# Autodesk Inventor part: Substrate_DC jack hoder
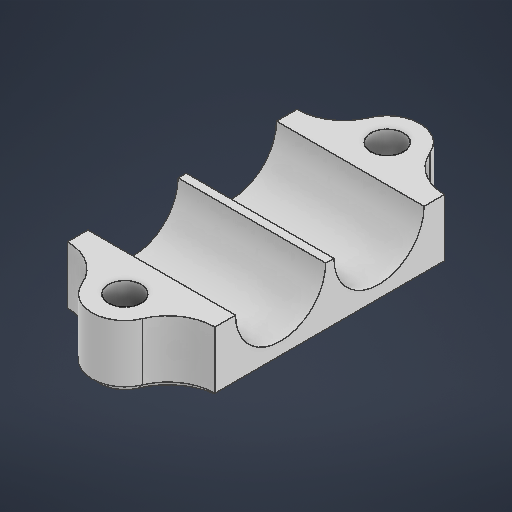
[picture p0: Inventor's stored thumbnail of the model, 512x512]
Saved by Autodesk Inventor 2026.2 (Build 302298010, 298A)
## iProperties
Created: 2026-04
Part Number: Substrate_DC jack hoder
Material: 일반
Document SubType Name: Modeling
Designer: work
Density: 1 g/cm^3
Appearance: 기본값
Author: work
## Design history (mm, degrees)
sketch "스케치1"
  geometry: L1 (0, 0)-(0, -12); L2 (0, -12)-(0, -20); L3 (0, -20)-(-8, -20); L4 (-8, -20)-(-8, 8); L5 (-8, 8)-(0, 8); L6 (0, 8)-(0, 0); C1 r 5.5 at (0, 0); C2 r 5.5 at (0, -12); 5 further points
  constraints: 12 end point, 3 perpendicular, 2 centre point, 2 coincident, 2 vertical, 1 horizontal
  dimensions: "d0" = 11 diameter of C1; "d1" = 12 distance of L1.start L1.end; "d2" = 11 diameter of C2; "d3" = 8 distance of L2.start L2.end; "d4" = 8 distance of L5.end L1.start; "d5" = 8 distance between parallel lines of L4 L6
extrude "돌출1" new body sketch "스케치1" distance "d6" = 18; taper "d7" = 0 deg
sketch "스케치2" dims "d9" = 8
  geometry: L1 (0, 2.5)-(0, 0) reference; L2 (0, 0)-(18, 0) reference; L3 (18, 2.5)-(18, 0) reference; L4 (0, 2.5)-(18, 2.5) reference; L5 (0, -23)-(18, -23) reference; L6 (0, -25.5)-(18, -25.5) reference; L7 (0, -11)-(0, -12) reference; L8 (0, -12)-(18, -12) reference; L9 (18, -11)-(18, -12) reference; L10 (0, -11)-(18, -11) reference; L11 (9, 2.5)-(9, -25.5); L12 (0, 2.5)-(18, 2.5) reference; L13 (18, -11.5)-(0, -11.5); L14 (9, -27.5)-(9, 4.5); C1 r 2 at (9, 4.5); C2 r 2 at (9, -27.5); A1 r 5.75 centre (0, 8.25) between (0, 2.5) and (5.308, 6.038); A2 r 5.75 centre (18, 8.25) between (12.692, 6.038) and (18, 2.5); A3 r 5.75 centre (18, -31.25) between (18, -25.5) and (12.692, -29.038); A4 r 5.75 centre (0, -31.25) between (5.308, -29.038) and (0, -25.5); 6 further points
  constraints: 8 point on circle, 8 symmetric about line, 6 centre point, 6 end point, 6 midpoint, 2 coincident, 1 horizontal, 1 tangent, 1 vertical, 11 other
  dimensions: "d8" = 4 diameter of C1; "d10" = 32 distance of C1.centre C2.centre
extrude "돌출2" join sketch "스케치2" stored distance "d11" = 18; taper "d12" = 0 deg
chamfer "모따기1" distance "d13" = 1; stored, may be unused: second distance "d14" = 2, angle "d15" = 45 deg
node "솔리드1"
node "투영된 루프1"
node "투영된 루프2"
